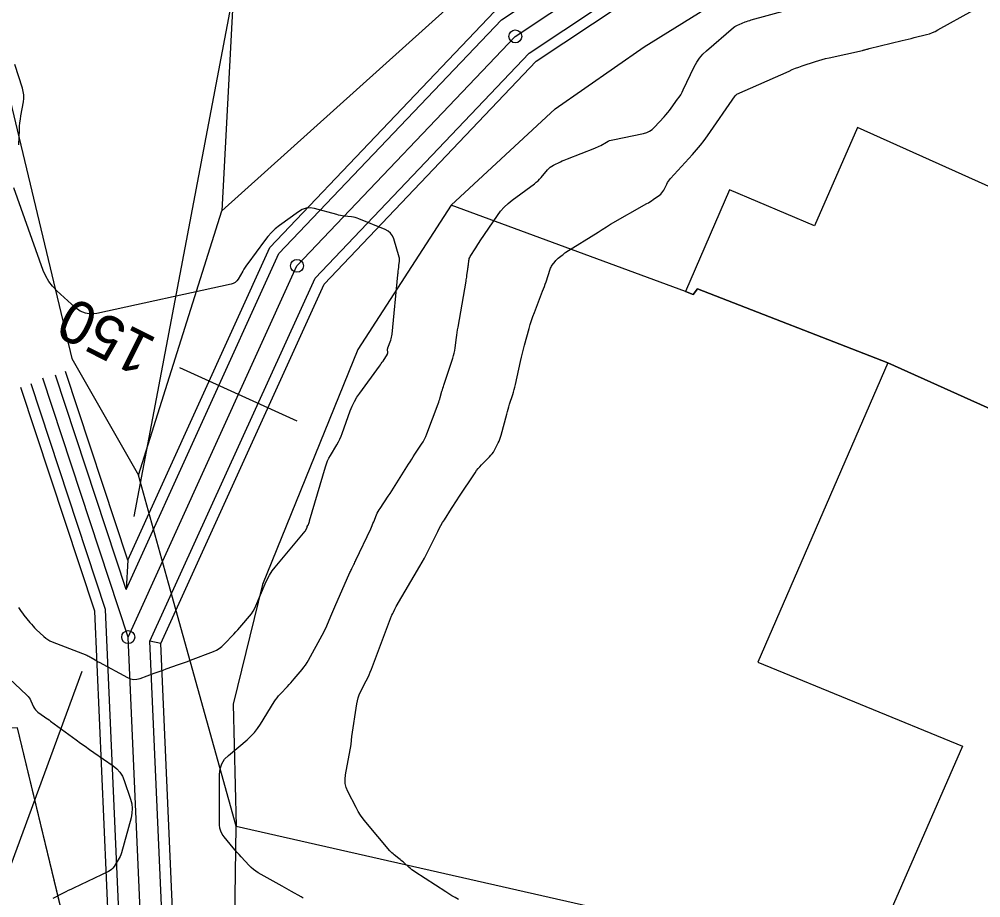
# Model space of a CAD drawing. Extents: x -534481 to -534256, y -1190577 to -1190138.
# Drawn here: x -534412.4 to -534390.06, y -1190397.49 to -1190377.09 of the extents above; entities that cross this region are included whole.
import ezdxf

# ---------------------------------------------------------------- set-up
doc = ezdxf.new("R2010")
doc.units = 0
for name, color, linetype in [('0_kroužky', 7, 'Continuous'), ('30', 7, 'Continuous'), ('31', 7, 'Continuous'), ('_N_osa', 7, 'Continuous'), ('_N_tenká', 7, 'Continuous'), ('_N_text', 7, 'Continuous'), ('_tenka', 7, 'Continuous'), ('Hranice parcel', 7, 'Continuous'), ('Polygon budovy', 7, 'Continuous')]:
    doc.layers.add(name, color=color, linetype=linetype)

msp = doc.modelspace()

# ---------------------------------------------------------------- linework, layer by layer
at = {"layer": '0_kroužky'}
for centre in [(-534400.873, -1190377.487), (-534400.873, -1190377.487), (-534400.873, -1190377.487), (-534400.873, -1190377.487), (-534400.873, -1190377.487), (-534400.873, -1190377.487), (-534405.947, -1190382.816), (-534405.947, -1190382.816), (-534405.947, -1190382.816), (-534405.947, -1190382.816), (-534405.947, -1190382.816), (-534405.947, -1190382.816), (-534409.868, -1190391.439), (-534409.868, -1190391.439), (-534409.868, -1190391.439), (-534409.868, -1190391.439), (-534409.868, -1190391.439), (-534409.868, -1190391.439)]:
    msp.add_circle(centre, 0.15, dxfattribs=at)
at = {"layer": '30'}
for points in [[(-534402.195, -1190397.53), (-534402.27, -1190397.488), (-534402.345, -1190397.445), (-534402.418, -1190397.4), (-534402.49, -1190397.354), (-534403.208, -1190396.889), (-534403.242, -1190396.866), (-534403.275, -1190396.842), (-534403.308, -1190396.816), (-534403.339, -1190396.789), (-534403.47, -1190396.67), (-534403.496, -1190396.647), (-534403.523, -1190396.624), (-534403.55, -1190396.602), (-534403.577, -1190396.581), (-534403.688, -1190396.497), (-534403.715, -1190396.475), (-534403.74, -1190396.452), (-534403.765, -1190396.427), (-534403.788, -1190396.401), (-534404.345, -1190395.738), (-534404.409, -1190395.657), (-534404.468, -1190395.573), (-534404.523, -1190395.486), (-534404.572, -1190395.396), (-534404.761, -1190395.028), (-534404.8, -1190394.935), (-534404.823, -1190394.84), (-534404.829, -1190394.742), (-534404.819, -1190394.641), (-534404.69, -1190393.934), (-534404.688, -1190393.918), (-534404.686, -1190393.903), (-534404.684, -1190393.887), (-534404.682, -1190393.871), (-534404.678, -1190393.808), (-534404.676, -1190393.793), (-534404.675, -1190393.777), (-534404.673, -1190393.761), (-534404.671, -1190393.746), (-534404.557, -1190392.99), (-534404.543, -1190392.918), (-534404.523, -1190392.848), (-534404.499, -1190392.78), (-534404.468, -1190392.713), (-534404.335, -1190392.451), (-534404.303, -1190392.384), (-534404.272, -1190392.318), (-534404.243, -1190392.25), (-534404.216, -1190392.181), (-534403.748, -1190390.942), (-534403.746, -1190390.934), (-534403.743, -1190390.928), (-534403.739, -1190390.921), (-534403.736, -1190390.914), (-534403.721, -1190390.887), (-534403.714, -1190390.874), (-534403.707, -1190390.861), (-534403.671, -1190390.787), (-534403.664, -1190390.773), (-534403.656, -1190390.759), (-534403.649, -1190390.744), (-534403.641, -1190390.73), (-534403.089, -1190389.789), (-534403.036, -1190389.697), (-534402.985, -1190389.604), (-534402.935, -1190389.511), (-534402.888, -1190389.416), (-534402.675, -1190388.985), (-534402.639, -1190388.915), (-534402.602, -1190388.847), (-534402.563, -1190388.779), (-534402.522, -1190388.713), (-534402.355, -1190388.449), (-534402.313, -1190388.383), (-534402.27, -1190388.317), (-534402.227, -1190388.252), (-534402.184, -1190388.187), (-534401.809, -1190387.622), (-534401.775, -1190387.573), (-534401.738, -1190387.526), (-534401.699, -1190387.481), (-534401.658, -1190387.438), (-534401.471, -1190387.252), (-534401.439, -1190387.217), (-534401.409, -1190387.18), (-534401.383, -1190387.141), (-534401.359, -1190387.099), (-534401.271, -1190386.929), (-534401.25, -1190386.886), (-534401.231, -1190386.843), (-534401.215, -1190386.798), (-534401.202, -1190386.752), (-534401.073, -1190386.259), (-534401.057, -1190386.201), (-534401.041, -1190386.144), (-534401.024, -1190386.087), (-534401.006, -1190386.03), (-534400.934, -1190385.804), (-534400.916, -1190385.747), (-534400.9, -1190385.689), (-534400.885, -1190385.632), (-534400.871, -1190385.574), (-534400.75, -1190385.036), (-534400.728, -1190384.941), (-534400.705, -1190384.845), (-534400.681, -1190384.75), (-534400.656, -1190384.655), (-534400.554, -1190384.275), (-534400.527, -1190384.18), (-534400.498, -1190384.087), (-534400.466, -1190383.994), (-534400.431, -1190383.902), (-534400.239, -1190383.408), (-534400.218, -1190383.352), (-534400.197, -1190383.296), (-534400.178, -1190383.24), (-534400.159, -1190383.184), (-534400.065, -1190382.896), (-534400.056, -1190382.871), (-534400.044, -1190382.847), (-534400.031, -1190382.823), (-534400.015, -1190382.801), (-534399.95, -1190382.714), (-534399.933, -1190382.693), (-534399.915, -1190382.673), (-534399.895, -1190382.654), (-534399.875, -1190382.636), (-534399.787, -1190382.566), (-534399.765, -1190382.549), (-534399.742, -1190382.532), (-534399.719, -1190382.517), (-534399.696, -1190382.501), (-534398.951, -1190382.034), (-534398.927, -1190382.019), (-534398.902, -1190382.004), (-534398.878, -1190381.988), (-534398.854, -1190381.972), (-534398.757, -1190381.91), (-534398.733, -1190381.895), (-534398.708, -1190381.88), (-534398.684, -1190381.865), (-534398.659, -1190381.85), (-534397.819, -1190381.372), (-534397.781, -1190381.35), (-534397.744, -1190381.327), (-534397.708, -1190381.303), (-534397.672, -1190381.279), (-534397.523, -1190381.175), (-534397.492, -1190381.151), (-534397.466, -1190381.123), (-534397.443, -1190381.092), (-534397.423, -1190381.058), (-534397.354, -1190380.916), (-534397.335, -1190380.881), (-534397.314, -1190380.848), (-534397.291, -1190380.816), (-534397.266, -1190380.786), (-534396.754, -1190380.228), (-534396.661, -1190380.124), (-534396.573, -1190380.016), (-534396.488, -1190379.906), (-534396.406, -1190379.793), (-534395.765, -1190378.869), (-534395.759, -1190378.861), (-534395.753, -1190378.855), (-534395.74, -1190378.842), (-534395.737, -1190378.838), (-534395.733, -1190378.836), (-534395.729, -1190378.833), (-534395.725, -1190378.831), (-534394.513, -1190378.291), (-534394.438, -1190378.258), (-534394.362, -1190378.228), (-534394.285, -1190378.199), (-534394.208, -1190378.173), (-534393.898, -1190378.07), (-534393.82, -1190378.045), (-534393.742, -1190378.022), (-534393.663, -1190378.002), (-534393.584, -1190377.983), (-534392.807, -1190377.813), (-534392.794, -1190377.81), (-534392.781, -1190377.806), (-534392.768, -1190377.803), (-534392.755, -1190377.799), (-534392.702, -1190377.785), (-534392.689, -1190377.781), (-534392.676, -1190377.778), (-534392.663, -1190377.774), (-534392.65, -1190377.771), (-534391.884, -1190377.586), (-534391.814, -1190377.569), (-534391.743, -1190377.551), (-534391.673, -1190377.534), (-534391.602, -1190377.516), (-534391.321, -1190377.444), (-534391.251, -1190377.424), (-534391.183, -1190377.399), (-534391.117, -1190377.37), (-534391.053, -1190377.337), (-534390.246, -1190376.885)], [(-534412.407, -1190380.004), (-534412.396, -1190379.656), (-534412.391, -1190379.574), (-534412.384, -1190379.492), (-534412.374, -1190379.411), (-534412.361, -1190379.33), (-534412.303, -1190379.006), (-534412.294, -1190378.926), (-534412.294, -1190378.846), (-534412.305, -1190378.767), (-534412.325, -1190378.688), (-534412.5, -1190378.142)], [(-534412.416, -1190390.749), (-534412.387, -1190390.796), (-534412.357, -1190390.842), (-534412.325, -1190390.886), (-534412.291, -1190390.929), (-534412.152, -1190391.099), (-534412.117, -1190391.141), (-534412.08, -1190391.182), (-534412.042, -1190391.221), (-534412.003, -1190391.259), (-534411.828, -1190391.425), (-534411.784, -1190391.462), (-534411.737, -1190391.495), (-534411.687, -1190391.524), (-534411.634, -1190391.547), (-534410.832, -1190391.861), (-534410.806, -1190391.872), (-534410.781, -1190391.883), (-534410.756, -1190391.896), (-534410.732, -1190391.91), (-534410.638, -1190391.968), (-534410.614, -1190391.983), (-534410.59, -1190391.997), (-534410.566, -1190392.01), (-534410.541, -1190392.024), (-534409.888, -1190392.376), (-534409.815, -1190392.406), (-534409.741, -1190392.42), (-534409.665, -1190392.417), (-534409.589, -1190392.397), (-534409.268, -1190392.28), (-534409.198, -1190392.254), (-534409.127, -1190392.229), (-534409.056, -1190392.204), (-534408.985, -1190392.179), (-534408.7, -1190392.079), (-534408.629, -1190392.054), (-534408.558, -1190392.029), (-534408.487, -1190392.003), (-534408.417, -1190391.976), (-534407.887, -1190391.771), (-534407.817, -1190391.74), (-534407.752, -1190391.702), (-534407.692, -1190391.657), (-534407.637, -1190391.604), (-534407.414, -1190391.371), (-534407.366, -1190391.32), (-534407.319, -1190391.268), (-534407.273, -1190391.216), (-534407.228, -1190391.163), (-534407.047, -1190390.951), (-534407.004, -1190390.896), (-534406.966, -1190390.839), (-534406.932, -1190390.779), (-534406.902, -1190390.716), (-534406.688, -1190390.203), (-534406.639, -1190390.099), (-534406.583, -1190389.998), (-534406.52, -1190389.903), (-534406.45, -1190389.811), (-534405.757, -1190388.976), (-534405.75, -1190388.967), (-534405.744, -1190388.958), (-534405.739, -1190388.949), (-534405.735, -1190388.939), (-534405.713, -1190388.887), (-534405.707, -1190388.874), (-534405.695, -1190388.849), (-534405.69, -1190388.836), (-534405.667, -1190388.781), (-534405.663, -1190388.771), (-534405.659, -1190388.76), (-534405.656, -1190388.749), (-534405.652, -1190388.738), (-534405.284, -1190387.484), (-534405.262, -1190387.415), (-534405.235, -1190387.348), (-534405.204, -1190387.283), (-534405.169, -1190387.22), (-534405.02, -1190386.97), (-534404.984, -1190386.906), (-534404.951, -1190386.842), (-534404.922, -1190386.775), (-534404.896, -1190386.708), (-534404.707, -1190386.182), (-534404.663, -1190386.073), (-534404.612, -1190385.969), (-534404.554, -1190385.868), (-534404.488, -1190385.771), (-534404.028, -1190385.145), (-534404.007, -1190385.116), (-534403.987, -1190385.087), (-534403.967, -1190385.057), (-534403.947, -1190385.027), (-534403.846, -1190384.866), (-534403.84, -1190384.855), (-534403.836, -1190384.844), (-534403.834, -1190384.832), (-534403.835, -1190384.82), (-534403.84, -1190384.77), (-534403.84, -1190384.758), (-534403.84, -1190384.746), (-534403.837, -1190384.734), (-534403.834, -1190384.722), (-534403.768, -1190384.542), (-534403.757, -1190384.508), (-534403.748, -1190384.473), (-534403.741, -1190384.438), (-534403.736, -1190384.402), (-534403.603, -1190383.024), (-534403.601, -1190383.006), (-534403.599, -1190382.988), (-534403.597, -1190382.97), (-534403.595, -1190382.952), (-534403.585, -1190382.88), (-534403.582, -1190382.862), (-534403.58, -1190382.844), (-534403.578, -1190382.827), (-534403.576, -1190382.809), (-534403.564, -1190382.706), (-534403.562, -1190382.683), (-534403.563, -1190382.66), (-534403.566, -1190382.638), (-534403.572, -1190382.615), (-534403.697, -1190382.188), (-534403.727, -1190382.116), (-534403.77, -1190382.055), (-534403.826, -1190382.007), (-534403.895, -1190381.97), (-534404.509, -1190381.724), (-534404.55, -1190381.709), (-534404.592, -1190381.697), (-534404.634, -1190381.688), (-534404.677, -1190381.681), (-534404.851, -1190381.66), (-534404.894, -1190381.654), (-534404.937, -1190381.647), (-534404.98, -1190381.638), (-534405.023, -1190381.627), (-534405.542, -1190381.488), (-534405.64, -1190381.472), (-534405.735, -1190381.479), (-534405.825, -1190381.507), (-534405.911, -1190381.558), (-534406.353, -1190381.882), (-534406.451, -1190381.96), (-534406.542, -1190382.045), (-534406.627, -1190382.137), (-534406.705, -1190382.235), (-534407.089, -1190382.758), (-534407.121, -1190382.801), (-534407.151, -1190382.846), (-534407.18, -1190382.891), (-534407.208, -1190382.938), (-534407.316, -1190383.124), (-534407.346, -1190383.166), (-534407.383, -1190383.2), (-534407.426, -1190383.224), (-534407.476, -1190383.24), (-534410.597, -1190383.921), (-534410.735, -1190383.936), (-534410.864, -1190383.918), (-534410.985, -1190383.868), (-534411.097, -1190383.787), (-534411.528, -1190383.394), (-534411.628, -1190383.291), (-534411.714, -1190383.178), (-534411.785, -1190383.056), (-534411.841, -1190382.924), (-534412.526, -1190381.007)]]:
    msp.add_lwpolyline(points, dxfattribs=at)
at = {"layer": '31'}
for points in [[(-534405.799, -1190397.504), (-534405.852, -1190397.471), (-534406.071, -1190397.344), (-534406.125, -1190397.313), (-534406.18, -1190397.282), (-534406.235, -1190397.251), (-534406.29, -1190397.22), (-534406.847, -1190396.911), (-534406.905, -1190396.876), (-534406.96, -1190396.836), (-534407.011, -1190396.792), (-534407.059, -1190396.743), (-534407.245, -1190396.54), (-534407.291, -1190396.489), (-534407.336, -1190396.438), (-534407.381, -1190396.386), (-534407.426, -1190396.334), (-534407.642, -1190396.079), (-534407.686, -1190396.016), (-534407.718, -1190395.95), (-534407.737, -1190395.878), (-534407.743, -1190395.802), (-534407.743, -1190394.625), (-534407.73, -1190394.497), (-534407.692, -1190394.381), (-534407.627, -1190394.277), (-534407.537, -1190394.185), (-534407.105, -1190393.823), (-534407.016, -1190393.742), (-534406.935, -1190393.655), (-534406.86, -1190393.562), (-534406.794, -1190393.462), (-534406.477, -1190392.946), (-534406.445, -1190392.896), (-534406.41, -1190392.848), (-534406.373, -1190392.802), (-534406.333, -1190392.758), (-534406.169, -1190392.586), (-534406.129, -1190392.543), (-534406.089, -1190392.499), (-534406.05, -1190392.454), (-534406.011, -1190392.409), (-534405.829, -1190392.193), (-534405.788, -1190392.141), (-534405.749, -1190392.087), (-534405.712, -1190392.031), (-534405.679, -1190391.974), (-534405.359, -1190391.391), (-534405.331, -1190391.338), (-534405.304, -1190391.285), (-534405.279, -1190391.231), (-534405.254, -1190391.176), (-534405.16, -1190390.955), (-534405.136, -1190390.9), (-534405.113, -1190390.845), (-534405.089, -1190390.79), (-534405.065, -1190390.735), (-534404.716, -1190389.942), (-534404.705, -1190389.918), (-534404.694, -1190389.894), (-534404.682, -1190389.87), (-534404.671, -1190389.846), (-534404.624, -1190389.75), (-534404.612, -1190389.726), (-534404.601, -1190389.702), (-534404.589, -1190389.678), (-534404.578, -1190389.654), (-534404.234, -1190388.923), (-534404.216, -1190388.884), (-534404.198, -1190388.844), (-534404.181, -1190388.804), (-534404.164, -1190388.764), (-534404.098, -1190388.603), (-534404.081, -1190388.563), (-534404.062, -1190388.524), (-534404.04, -1190388.486), (-534404.017, -1190388.45), (-534403.824, -1190388.162), (-534403.784, -1190388.102), (-534403.744, -1190388.042), (-534403.705, -1190387.981), (-534403.666, -1190387.92), (-534403.355, -1190387.424), (-534403.318, -1190387.365), (-534403.281, -1190387.307), (-534403.243, -1190387.249), (-534403.205, -1190387.191), (-534403.053, -1190386.96), (-534403.017, -1190386.901), (-534402.984, -1190386.841), (-534402.954, -1190386.779), (-534402.928, -1190386.715), (-534402.667, -1190386.018), (-534402.654, -1190385.983), (-534402.641, -1190385.947), (-534402.63, -1190385.911), (-534402.619, -1190385.875), (-534402.577, -1190385.73), (-534402.567, -1190385.694), (-534402.556, -1190385.658), (-534402.544, -1190385.622), (-534402.533, -1190385.586), (-534402.326, -1190384.96), (-534402.308, -1190384.902), (-534402.293, -1190384.843), (-534402.281, -1190384.784), (-534402.272, -1190384.724), (-534402.241, -1190384.483), (-534402.232, -1190384.423), (-534402.224, -1190384.363), (-534402.214, -1190384.303), (-534402.204, -1190384.243), (-534402.019, -1190383.175), (-534402.013, -1190383.142), (-534402.008, -1190383.109), (-534402.003, -1190383.076), (-534401.998, -1190383.043), (-534401.977, -1190382.895), (-534401.974, -1190382.87), (-534401.971, -1190382.844), (-534401.967, -1190382.819), (-534401.964, -1190382.794), (-534401.953, -1190382.692), (-534401.949, -1190382.667), (-534401.942, -1190382.642), (-534401.932, -1190382.619), (-534401.92, -1190382.597), (-534401.794, -1190382.398), (-534401.768, -1190382.357), (-534401.742, -1190382.317), (-534401.716, -1190382.277), (-534401.689, -1190382.238), (-534401.288, -1190381.647), (-534401.214, -1190381.547), (-534401.132, -1190381.455), (-534401.043, -1190381.369), (-534400.946, -1190381.291), (-534400.427, -1190380.908), (-534400.385, -1190380.875), (-534400.346, -1190380.84), (-534400.308, -1190380.803), (-534400.273, -1190380.763), (-534400.126, -1190380.589), (-534400.095, -1190380.556), (-534400.062, -1190380.527), (-534400.026, -1190380.502), (-534399.986, -1190380.48), (-534399.824, -1190380.4), (-534399.783, -1190380.38), (-534399.742, -1190380.361), (-534399.701, -1190380.344), (-534399.659, -1190380.327), (-534399.028, -1190380.085), (-534398.992, -1190380.07), (-534398.957, -1190380.054), (-534398.922, -1190380.037), (-534398.888, -1190380.018), (-534398.753, -1190379.941), (-534398.718, -1190379.923), (-534398.683, -1190379.908), (-534398.646, -1190379.896), (-534398.609, -1190379.887), (-534397.893, -1190379.74), (-534397.821, -1190379.719), (-534397.755, -1190379.689), (-534397.694, -1190379.648), (-534397.639, -1190379.597), (-534397.415, -1190379.355), (-534397.372, -1190379.307), (-534397.33, -1190379.258), (-534397.29, -1190379.208), (-534397.252, -1190379.156), (-534397.101, -1190378.948), (-534397.065, -1190378.896), (-534397.031, -1190378.841), (-534396.999, -1190378.786), (-534396.971, -1190378.728), (-534396.716, -1190378.192), (-534396.659, -1190378.087), (-534396.593, -1190377.99), (-534396.516, -1190377.901), (-534396.429, -1190377.819), (-534395.8, -1190377.284), (-534395.771, -1190377.261), (-534395.74, -1190377.24), (-534395.707, -1190377.223), (-534395.673, -1190377.208), (-534395.533, -1190377.152), (-534395.498, -1190377.139), (-534395.462, -1190377.127), (-534395.426, -1190377.115), (-534395.39, -1190377.105), (-534394.568, -1190376.878)], [(-534412.776, -1190392.272), (-534412.222, -1190392.79), (-534412.195, -1190392.818), (-534412.17, -1190392.849), (-534412.149, -1190392.882), (-534412.131, -1190392.917), (-534412.065, -1190393.061), (-534412.046, -1190393.095), (-534412.024, -1190393.127), (-534411.997, -1190393.155), (-534411.967, -1190393.179), (-534411.815, -1190393.287), (-534411.779, -1190393.313), (-534411.743, -1190393.338), (-534411.707, -1190393.364), (-534411.672, -1190393.39), (-534411.08, -1190393.824), (-534410.976, -1190393.899), (-534410.872, -1190393.973), (-534410.768, -1190394.047), (-534410.663, -1190394.12), (-534410.219, -1190394.427), (-534410.132, -1190394.497), (-534410.06, -1190394.578), (-534410.003, -1190394.669), (-534409.959, -1190394.772), (-534409.815, -1190395.204), (-534409.787, -1190395.312), (-534409.776, -1190395.42), (-534409.781, -1190395.529), (-534409.803, -1190395.639), (-534410.026, -1190396.451), (-534410.039, -1190396.494), (-534410.056, -1190396.535), (-534410.075, -1190396.576), (-534410.098, -1190396.615), (-534410.196, -1190396.768), (-534410.222, -1190396.804), (-534410.253, -1190396.835), (-534410.287, -1190396.862), (-534410.326, -1190396.883), (-534411.138, -1190397.27), (-534411.199, -1190397.299), (-534411.26, -1190397.328), (-534411.32, -1190397.358), (-534411.381, -1190397.388), (-534411.622, -1190397.509)]]:
    msp.add_lwpolyline(points, dxfattribs=at)
at = {"layer": '_N_osa'}
for points in [[(-534409.868, -1190391.439), (-534405.947, -1190382.816), (-534400.873, -1190377.487), (-534393.696, -1190372.718), (-534384.927, -1190365.477), (-534382.631, -1190361.148), (-534355.894, -1190347.823), (-534351.738, -1190342.389), (-534351.577, -1190328.316), (-534347.204, -1190300.921), (-534345.553, -1190283.64), (-534344.682, -1190264.494)], [(-534409.868, -1190391.439), (-534411.855, -1190385.422)], [(-534408.105, -1190518.46), (-534393.616, -1190502.389), (-534391.346, -1190496.962), (-534392.763, -1190488.017), (-534396.655, -1190477.752), (-534402.513, -1190464.283), (-534404.757, -1190456.741), (-534408.311, -1190433.088), (-534409.248, -1190427.879), (-534409.316, -1190416.054), (-534409.076, -1190409.418), (-534409.868, -1190391.439)]]:
    msp.add_lwpolyline(points, dxfattribs=at)
at = {"layer": '_N_tenká'}
for p, q in [((-534409.879, -1190389.652), (-534409.916, -1190390.337)), ((-534409.111, -1190391.586), (-534409.363, -1190391.537))]:
    msp.add_line(p, q, dxfattribs=at)
for points in [[(-534409.916, -1190390.337), (-534406.368, -1190382.532), (-534401.196, -1190377.102), (-534393.995, -1190372.316), (-534385.322, -1190365.155), (-534382.997, -1190360.772), (-534356.221, -1190347.427), (-534352.236, -1190342.217), (-534352.076, -1190328.274), (-534347.7, -1190300.857), (-534346.052, -1190283.605), (-534345.255, -1190266.096)], [(-534409.879, -1190389.652), (-534406.578, -1190382.39), (-534401.358, -1190376.909), (-534394.144, -1190372.115), (-534385.52, -1190364.994), (-534383.181, -1190360.584), (-534356.384, -1190347.229), (-534352.485, -1190342.131), (-534352.326, -1190328.253), (-534347.948, -1190300.826), (-534346.301, -1190283.588), (-534345.507, -1190266.125)], [(-534409.363, -1190391.537), (-534405.527, -1190383.099), (-534400.549, -1190377.873), (-534393.398, -1190373.12), (-534384.532, -1190365.799), (-534382.264, -1190361.524), (-534355.568, -1190348.219), (-534351.24, -1190342.56), (-534351.077, -1190328.359), (-534346.708, -1190300.984), (-534345.054, -1190283.675), (-534344.256, -1190266.142)], [(-534409.111, -1190391.586), (-534405.317, -1190383.241), (-534400.388, -1190378.065), (-534393.249, -1190373.321), (-534384.335, -1190365.96), (-534382.081, -1190361.712), (-534355.404, -1190348.417), (-534350.991, -1190342.646), (-534350.828, -1190328.38), (-534346.46, -1190301.016), (-534344.805, -1190283.693), (-534344.008, -1190266.196)]]:
    msp.add_lwpolyline(points, dxfattribs=at)
at = {"layer": '_N_text'}
for points in [[(-534409.732, -1190388.64), (-534397.101, -1190322.153), (-534346.296, -1190265.502)], [(-534405.94, -1190386.425), (-534408.672, -1190385.183)], [(-534406.078, -1190512.511), (-534434.703, -1190456.89), (-534410.94, -1190392.232)]]:
    msp.add_lwpolyline(points, dxfattribs=at)
at = {"layer": '_tenka'}
for points in [[(-534409.879, -1190389.652), (-534411.326, -1190385.272)], [(-534409.916, -1190390.337), (-534411.561, -1190385.357)], [(-534410.645, -1190390.84), (-534412.361, -1190385.645)], [(-534410.397, -1190390.795), (-534412.125, -1190385.56)], [(-534405.407, -1190514.348), (-534394.258, -1190501.982), (-534392.12, -1190496.869), (-534393.492, -1190488.211), (-534397.35, -1190478.035), (-534403.219, -1190464.54), (-534405.491, -1190456.905), (-534409.051, -1190433.21), (-534409.998, -1190427.948), (-534410.066, -1190416.042), (-534409.827, -1190409.421), (-534410.645, -1190390.84)], [(-534405.057, -1190514.333), (-534394.044, -1190502.118), (-534391.862, -1190496.9), (-534393.249, -1190488.146), (-534397.118, -1190477.94), (-534402.983, -1190464.455), (-534405.247, -1190456.85), (-534408.804, -1190433.17), (-534409.748, -1190427.925), (-534409.816, -1190416.046), (-534409.577, -1190409.42), (-534410.397, -1190390.795)], [(-534403.656, -1190514.273), (-534393.187, -1190502.661), (-534390.83, -1190497.024), (-534392.278, -1190487.888), (-534396.191, -1190477.563), (-534402.042, -1190464.111), (-534404.268, -1190456.632), (-534407.818, -1190433.007), (-534408.749, -1190427.833), (-534408.816, -1190416.061), (-534408.576, -1190409.416), (-534409.363, -1190391.537)], [(-534403.306, -1190514.257), (-534392.973, -1190502.796), (-534390.572, -1190497.055), (-534392.035, -1190487.824), (-534395.96, -1190477.469), (-534401.807, -1190464.025), (-534404.023, -1190456.578), (-534407.571, -1190432.966), (-534408.499, -1190427.81), (-534408.566, -1190416.065), (-534408.326, -1190409.415), (-534409.111, -1190391.586)]]:
    msp.add_lwpolyline(points, dxfattribs=at)
at = {"layer": 'Hranice parcel'}
for p, q in [((-534409.63, -1190387.68), (-534407.69, -1190381.54)), ((-534410.38, -1190402.1), (-534412.44, -1190393.55)), ((-534407.5, -1190405.6), (-534407.36, -1190395.83)), ((-534407.36, -1190395.83), (-534397.83, -1190397.99))]:
    msp.add_line(p, q, dxfattribs=at)
for points in [[(-534425.49, -1190303.95), (-534427.4, -1190310.23), (-534432.23, -1190329.13), (-534431.92, -1190332.1), (-534423.51, -1190345.02), (-534415.2, -1190368.18), (-534411.18, -1190384.97), (-534409.63, -1190387.68)], [(-534403.65, -1190306.96), (-534404.41, -1190319.66), (-534407.69, -1190381.54)], [(-534407.69, -1190381.54), (-534401.89, -1190376.32), (-534395.25, -1190371.93), (-534386.83, -1190364.89)], [(-534402.36, -1190381.41), (-534399.95, -1190379.17), (-534397.88, -1190377.73), (-534391.57, -1190373.81)], [(-534402.36, -1190381.41), (-534404.53, -1190384.76), (-534406.75, -1190390.22), (-534407.43, -1190393), (-534407.36, -1190395.83)], [(-534379.97, -1190390.57), (-534392.22, -1190385.07), (-534396.64, -1190383.35), (-534396.74, -1190383.48), (-534396.92, -1190383.41), (-534402.36, -1190381.41)], [(-534407.36, -1190395.83), (-534408.93, -1190390.19), (-534409.24, -1190389.07), (-534409.63, -1190387.68)]]:
    msp.add_lwpolyline(points, dxfattribs=at)
at = {"layer": 'Polygon budovy'}
for points in [[(-534396.92, -1190383.41), (-534396.74, -1190383.48), (-534396.64, -1190383.35), (-534392.22, -1190385.07), (-534379.97, -1190390.57), (-534376.9, -1190383.06), (-534381.11, -1190380.27), (-534381.65, -1190379.91), (-534382.92, -1190382.23), (-534383.75, -1190383.73), (-534388.06, -1190381.79), (-534392.92, -1190379.6), (-534393.92, -1190381.89), (-534395.9, -1190381.05)], [(-534392.73, -1190399.11), (-534384.27, -1190400.73), (-534379.97, -1190390.57), (-534392.22, -1190385.07), (-534395.24, -1190392.02), (-534390.48, -1190393.97)], [(-534432.64, -1190394.16), (-534432.33, -1190402.39), (-534427.61, -1190402.33), (-534427.86, -1190398.67), (-534414.87, -1190398.34), (-534413.97, -1190398.32), (-534413.47, -1190402.14), (-534410.38, -1190402.1), (-534412.44, -1190393.55), (-534415.89, -1190393.7), (-534421.6, -1190393.94), (-534427.8, -1190394.2)]]:
    msp.add_lwpolyline(points, close=True, dxfattribs=at)

# ---------------------------------------------------------------- texts
at = {"layer": '_N_text'}
msp.add_text('150', height=1, rotation=153.4033, dxfattribs=at).set_placement((-534409.166, -1190384.52))

doc.saveas('drawing.dxf')
